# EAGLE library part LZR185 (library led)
LED BLOCK 5 LEDs, Siemens
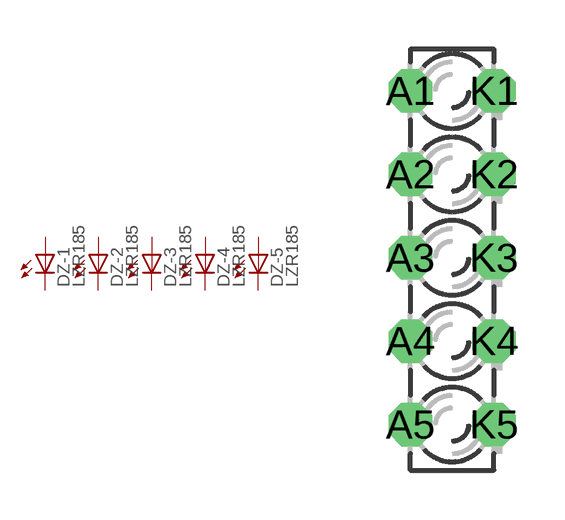
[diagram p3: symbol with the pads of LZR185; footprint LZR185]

Designator prefix DZ; gates -1=LED -2=LED -3=LED -4=LED -5=LED

## LZR185  [LZR185]
A1  -1:A  pas
A2  -2:A  pas
A3  -3:A  pas
A4  -4:A  pas
A5  -5:A  pas
K1  -1:C  pas
K2  -2:C  pas
K3  -3:C  pas
K4  -4:C  pas
K5  -5:C  pas

## Footprint LZR185 (pad centres in mm)
LED BLOCK 5 LEDs, Siemens
drill 0.813 octagon: A1 -1.27,5.08; A2 -1.27,2.54; A3 -1.27,0; A4 -1.27,-2.54; A5 -1.27,-5.08; K1 1.27,5.08; K2 1.27,2.54; K3 1.27,0; K4 1.27,-2.54; K5 1.27,-5.08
